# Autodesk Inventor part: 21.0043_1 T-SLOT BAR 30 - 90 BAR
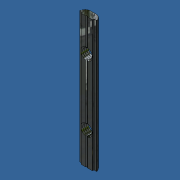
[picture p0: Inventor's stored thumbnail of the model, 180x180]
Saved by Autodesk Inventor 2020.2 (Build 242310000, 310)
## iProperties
Created: 2020-11
Part Number: 21.0043_1 T-SLOT BAR 30 - 90 BAR
Material: Steel
Document SubType Name: Modeling
Designer: amoles
Density: 7.85 g/cm^3
Appearance: Zinc
Author: amoles
Revision Number: -
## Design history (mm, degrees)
feature "Volumenkörper2"
body "Solid1"
